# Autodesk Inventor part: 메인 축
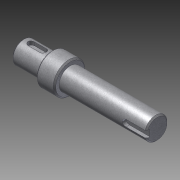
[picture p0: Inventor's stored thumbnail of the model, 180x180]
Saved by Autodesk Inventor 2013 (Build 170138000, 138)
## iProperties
Created: 2016-04
Part Number: 메인 축
Document SubType Name: Modeling
Designer: mdu
Density: 7.86 g/cm^3
Mass: 230.24 g
Surface Area: 74.3518 cm^2
Volume: 29.2926 cm^3
Material: 강철, 연강
Author: mdu
Revision Number: 1
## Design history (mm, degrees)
sketch "스케치1"
  geometry: L1 (10.497, -57.5)-(112.497, -57.5); L2 (10.497, -66)-(32.497, -66); L3 (32.497, -69.5)-(46.5, -69.5); L4 (46.5, -66)-(112.497, -66); L5 (112.497, -66)-(112.497, -57.5); L6 (10.497, -66)-(10.497, -57.5); L7 (46.5, -69.749)-(46.5, -45.251) reference; L8 (46.5, -69.5)-(46.5, -66); L9 (32.497, -69.5)-(32.497, -66); L10 (32.497, -35)-(32.497, -80) reference; 3 further points
  constraints: 16 end point, 3 point on line, 2 parallel, 2 perpendicular, 1 collinear, 1 horizontal, 1 midpoint
  dimensions: "d0" = 17 diameter of L4 L1; "d1" = 24 diameter of L3 L1; "d2" = 22 distance of L2.start L2.end; "d3" = 65.99692 distance of L4.start L4.end (derived); "d5" = 17 diameter of L2 L1; "d19" = 80 distance between parallel lines of L5 L9
revolve "회전1" sketch "스케치1" stored, may be unused: angle "d4" = 90 deg
feature "면 이동1"
chamfer "모따기1" distance "d6" = 0.5; stored, may be unused: second distance "d7" = 2, angle "d8" = 45 deg
node "작업 평면1"
sketch "스케치2"
  geometry: L1 (-11, -8)-(-11, 8) reference; L2 (-4.5, 2.5)-(4.5, 2.5); L3 (4.5, -2.5)-(-4.5, -2.5); A1 r 2.5 centre (4.5, 0) between (4.5, -2.5) and (4.5, 2.5); A2 r 2.5 centre (-4.5, 0) between (-4.5, 2.5) and (-4.5, -2.5); 2 further points
  constraints: 4 end point, 4 point on circle, 4 tangent, 2 centre point, 1 horizontal alignment, 1 midpoint, 1 parallel, 1 perpendicular
  dimensions: "d9" = 5 distance between parallel lines of L3 L2; "d10" = 14 dimension on A1 A2; "d11" = 4 distance edge to line of A2 L1
extrude "돌출1" cut sketch "스케치2" distance "d12" = 3; taper "d13" = 0 deg
node "작업 평면2"
sketch "스케치3"
  geometry: L1 (32.998, 8)-(32.998, -8) reference; L2 (32.998, 2.5)-(17.498, 2.5); L3 (17.498, -2.5)-(32.998, -2.5); A1 r 2.5 centre (17.498, 0) between (17.498, 2.5) and (17.498, -2.5); 2 further points
  constraints: 4 end point, 2 perpendicular, 2 point on circle, 2 point on line, 2 tangent, 1 centre point, 1 horizontal alignment, 1 midpoint
  dimensions: "d14" = 5 distance between parallel lines of L3 L2; "d15" = 18 dimension on A1 L1
extrude "돌출2" cut sketch "스케치3" distance "d16" = 3; taper "d17" = 0 deg
node "솔리드1"
node "참조4"
node "참조5"
